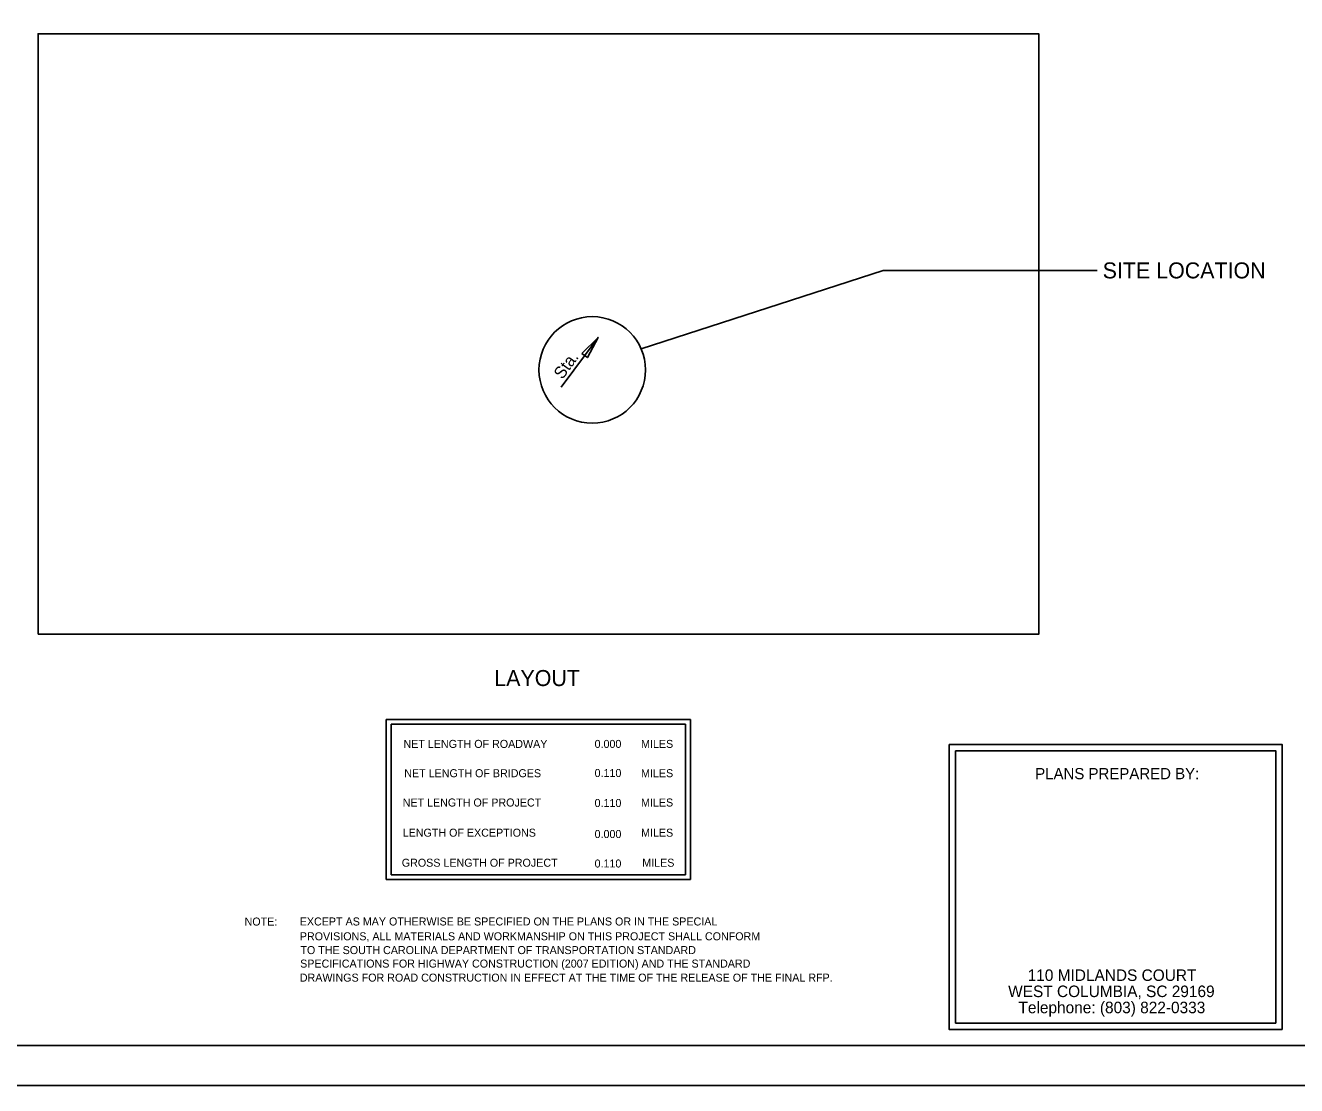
# Model space of a CAD drawing. Extents: x -1142 to 658, y -589 to 511.
# Drawn here: x -534 to 260, y -589 to 73 of the extents above; entities that cross this region are included whole.
import ezdxf

# ---------------------------------------------------------------- set-up
doc = ezdxf.new("R2010")
doc.units = 0
for name, color, linetype in [('BR_BORDER LINES', 7, 'Continuous'), ('BR_REBAR', 7, 'Continuous'), ('Default', 7, 'Continuous'), ('Level 31', 7, 'Continuous'), ('RD_SHT_IplotShp', 7, 'Continuous')]:
    doc.layers.add(name, color=color, linetype=linetype)

msp = doc.modelspace()

# ---------------------------------------------------------------- linework, layer by layer
at = {"layer": 'BR_BORDER LINES'}
msp.add_line((-1041.79, -564.26), (633.21, -564.26), dxfattribs=at)
at = {"layer": 'BR_REBAR'}
for p, q in [((1.78, -80.34), (-149.28, -129.26)), ((1.78, -80.34), (135.59, -80.34)), ((-199.25, -153.25), (-176.22, -122.12))]:
    msp.add_line(p, q, dxfattribs=at)
msp.add_lwpolyline([(-186.28, -132.17), (-176.22, -122.12), (-182.89, -134.68)], close=True, dxfattribs=at)
msp.add_circle((-179.87, -142.4), 33.27, dxfattribs=at)
at = {"layer": 'Default'}
for p, q in [((-118.53, -360.66), (-308.53, -360.66)), ((-308.53, -360.66), (-308.53, -460.66)), ((-121.53, -363.66), (-305.53, -363.66)), ((-305.53, -363.66), (-305.53, -457.71)), ((-121.53, -457.71), (-121.53, -363.66)), ((-118.53, -460.66), (-118.53, -360.66)), ((-305.48, -457.66), (-121.53, -457.66)), ((-308.53, -460.66), (-118.53, -460.66))]:
    msp.add_line(p, q, dxfattribs=at)
for points in [[(-526.03, -307.45), (98.97, -307.45), (98.97, 67.55), (-526.03, 67.55)], [(43.05, -376.26), (251.05, -376.26), (251.05, -554.26), (43.05, -554.26)], [(47.05, -380.26), (247.05, -380.26), (247.05, -550.26), (47.05, -550.26)]]:
    msp.add_lwpolyline(points, close=True, dxfattribs=at)
at = {"layer": 'Level 31'}
msp.add_lwpolyline([(-1141.79, 510.67), (-1141.79, -589.33), (658.21, -589.33), (658.21, 510.67)], dxfattribs=at)
at = {"layer": 'RD_SHT_IplotShp'}
msp.add_line((-1141.79, -589.26), (658.21, -589.26), dxfattribs=at)

# ---------------------------------------------------------------- texts
at = {"layer": 'BR_REBAR'}
msp.add_text('Sta.', height=7.5, rotation=53.74705, dxfattribs=at).set_placement((-198.5, -148.77))
at = {"layer": 'Default'}
for s, height, p in [('SITE LOCATION', 10, (138.93, -85.26)), ('LAYOUT', 10, (-241.07, -339.83)), ('NET LENGTH OF ROADWAY', 5.0001, (-297.78, -378.46)), ('0.000', 5, (-178.41, -378.46)), ('MILES', 5, (-149.38, -378.46)), ('NET LENGTH OF BRIDGES', 5.0001, (-297.28, -396.76)), ('0.110', 5, (-178.41, -396.63)), ('MILES', 5, (-149.39, -396.76)), ('PLANS PREPARED BY:', 7, (96.8, -398.01)), ('NET LENGTH OF PROJECT', 5.0001, (-298.28, -415.06)), ('0.110', 5, (-178.41, -415.36)), ('MILES', 5, (-149.4, -415.06)), ('LENGTH OF EXCEPTIONS', 5.0001, (-298.28, -433.91)), ('0.000', 5, (-178.41, -434.73)), ('MILES', 5, (-149.37, -433.91)), ('GROSS LENGTH OF PROJECT', 5.0001, (-298.83, -452.66)), ('0.110', 5, (-178.41, -453.14)), ('MILES', 5, (-148.63, -452.66)), ('EXCEPT AS MAY OTHERWISE BE SPECIFIED ON THE PLANS OR IN THE SPECIAL ', 5.0001, (-362.56, -489.35)), ('NOTE:', 5, (-397.02, -489.41)), ('PROVISIONS, ALL MATERIALS AND WORKMANSHIP ON THIS PROJECT SHALL CONFORM ', 5.0001, (-362.51, -498.6)), ('TO THE SOUTH CAROLINA DEPARTMENT OF TRANSPORTATION STANDARD ', 5.0001, (-362.15, -507.22)), ('SPECIFICATIONS FOR HIGHWAY CONSTRUCTION (2007 EDITION) AND THE STANDARD', 5.0001, (-362.31, -515.65)), ('DRAWINGS FOR ROAD CONSTRUCTION IN EFFECT AT THE TIME OF THE RELEASE OF THE FINAL RFP.', 5.0001, (-362.53, -524.42)), ('110 MIDLANDS COURT', 7.2, (92.09, -523.99)), ('WEST COLUMBIA, SC 29169', 7.2, (79.91, -534.07)), ('Telephone: (803) 822-0333', 7.2, (86.35, -544.15))]:
    msp.add_text(s, height=height, dxfattribs=at).set_placement(p)

doc.saveas('drawing.dxf')
